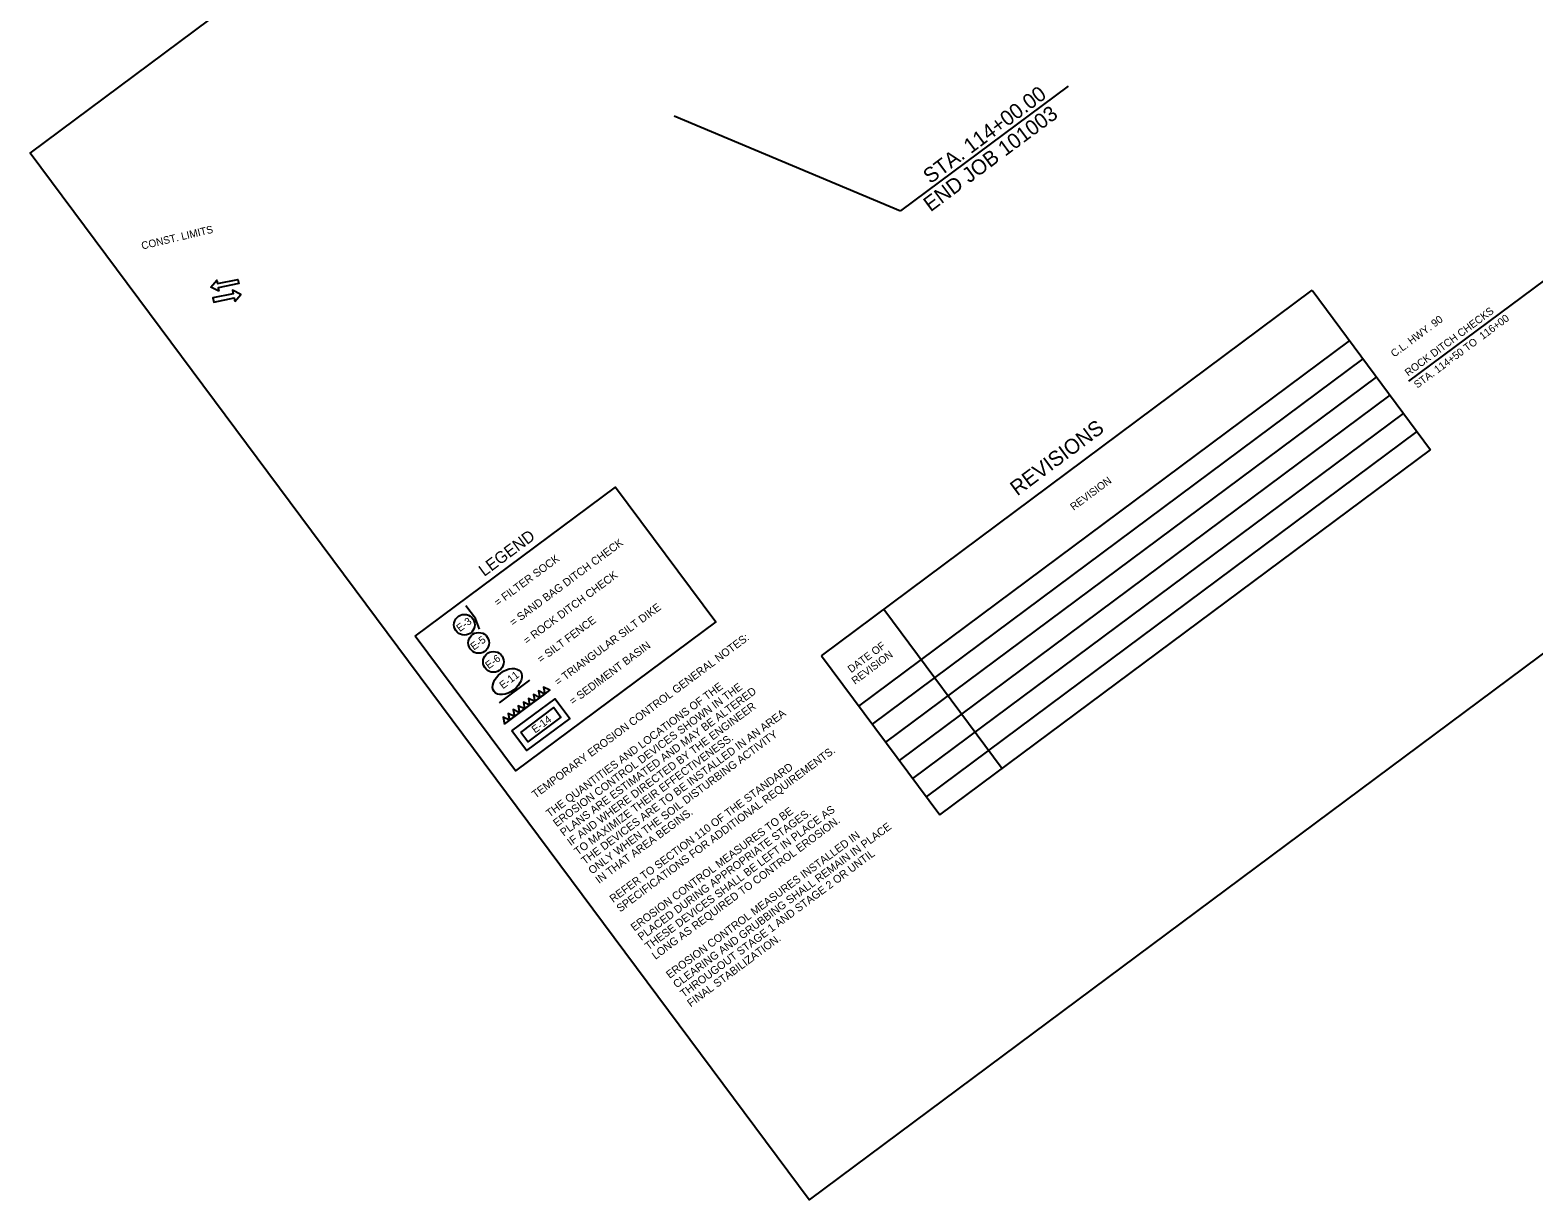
# Model space of a CAD drawing. Extents: x 1571137 to 1573037, y 731597 to 733459.
# Drawn here: x 1571137 to 1572334, y 731597 to 732528 of the extents above; entities that cross this region are included whole.
import ezdxf

# ---------------------------------------------------------------- set-up
doc = ezdxf.new("R2010")
doc.units = 0
for name, color, linetype in [('Default', 7, 'Continuous'), ('R_Annotation', 7, 'Continuous'), ('R_Erosion', 7, 'Continuous'), ('R_Erosion_STG 2', 7, 'Continuous'), ('R_MOT', 7, 'Continuous'), ('S_BASELINE', 7, 'Continuous'), ('S_MSC_PT_SYM', 7, 'Continuous')]:
    doc.layers.add(name, color=color, linetype=linetype)

msp = doc.modelspace()

# ---------------------------------------------------------------- linework, layer by layer
at = {"layer": 'Default'}
msp.add_lwpolyline([(1571510.5, 731992.8), (1571534.7, 732010.8)], dxfattribs=at)
at = {"layer": 'R_Annotation'}
for p, q in [((1571963.2, 732483.5), (1571829.7, 732384.2)), ((1571649.5, 732459.7), (1571829.7, 732384.2)), ((1572234.2, 732248.7), (1572469.2, 732423.5))]:
    msp.add_line(p, q, dxfattribs=at)
msp.add_lwpolyline([(1571443.5, 732045.9), (1571602.8, 732164.5), (1571682.7, 732057.2), (1571523.3, 731938.6)], close=True, dxfattribs=at)
at = {"layer": 'R_Erosion'}
msp.add_line((1571514.5, 731975.9), (1571550.6, 732002.8), dxfattribs=at)
for points in [[(1571494.7, 732051.4), (1571491.4, 732059.8), (1571483.8, 732069.9)], [(1571514.5, 731975.9), (1571550.6, 732002.8)]]:
    msp.add_lwpolyline(points, dxfattribs=at)
for points in [[(1571538.6, 731993.8), (1571542.6, 731996.8), (1571537.6, 731999.3)], [(1571542.6, 731996.8), (1571546.6, 731999.8), (1571541.6, 732002.3)], [(1571546.6, 731999.8), (1571550.6, 732002.8), (1571545.6, 732005.3)], [(1571520.4, 731970.4), (1571554.8, 731996), (1571566.4, 731980.4), (1571532, 731954.8)], [(1571522.5, 731981.9), (1571526.5, 731984.9), (1571521.5, 731987.4)], [(1571526.5, 731984.9), (1571530.5, 731987.9), (1571525.5, 731990.4)], [(1571527.4, 731969.3), (1571553.8, 731989), (1571559.4, 731981.4), (1571533, 731961.8)], [(1571530.5, 731987.9), (1571534.5, 731990.8), (1571529.6, 731993.4)], [(1571534.5, 731990.8), (1571538.6, 731993.8), (1571533.6, 731996.3)], [(1571514.5, 731975.9), (1571518.5, 731978.9), (1571513.5, 731981.4)], [(1571518.5, 731978.9), (1571522.5, 731981.9), (1571517.5, 731984.4)]]:
    msp.add_lwpolyline(points, close=True, dxfattribs=at)
for centre in [(1571482.6, 732054.9), (1571494, 732040.5), (1571505.7, 732025.4)]:
    msp.add_circle(centre, 8.26, dxfattribs=at)
msp.add_ellipse((1571516.7, 732009.7), major_axis=(10.5, 8), ratio=0.638788, dxfattribs=at)
at = {"layer": 'R_MOT'}
for points in [[(1571287.3, 732320.3), (1571280.7, 732323.5), (1571285.5, 732329.1), (1571286.1, 732326.3), (1571302.3, 732329.6), (1571303, 732326.3), (1571286.7, 732323)], [(1571299.8, 732312.2), (1571304.7, 732317.7), (1571298.1, 732321), (1571298.6, 732318.2), (1571282.4, 732315), (1571283.1, 732311.7), (1571299.3, 732314.9)]]:
    msp.add_lwpolyline(points, close=True, dxfattribs=at)
at = {"layer": 'S_BASELINE'}
for p, q in [((1571766.7, 732030.3), (1572157.2, 732321)), ((1572157.2, 732321), (1572251.5, 732194.2)), ((1571796.5, 731990.2), (1572187.1, 732280.9)), ((1571807.3, 731975.8), (1572197.8, 732266.4)), ((1571818, 731961.4), (1572208.5, 732252)), ((1571828.8, 731946.9), (1572219.3, 732237.6)), ((1571839.5, 731932.5), (1572230, 732223.1)), ((1571850.3, 731918), (1572240.8, 732208.7)), ((1571861, 731903.6), (1572251.5, 732194.2)), ((1571816.3, 732067.2), (1571910.6, 731940.5)), ((1571766.7, 732030.3), (1571861, 731903.6))]:
    msp.add_line(p, q, dxfattribs=at)
at = {"layer": 'S_MSC_PT_SYM'}
msp.add_lwpolyline([(1572536.7, 733221.6), (1573036.7, 732549.8), (1571756.9, 731597.3), (1571137, 732430.2), (1572086.8, 733137.2), (1572116.3, 733097.5), (1572258.8, 733203.6), (1572269.5, 733189.2), (1572284.1, 733200.1), (1572282.1, 733202.7), (1572344.4, 733249.1)], dxfattribs=at)

# ---------------------------------------------------------------- texts
at = {"layer": 'Default'}
for s, height, p in [('LEGEND', 9.37, (1571498.4, 732092.9)), ('= SAND BAG DITCH CHECK', 6.25, (1571521.5, 732053.4)), ('= FILTER SOCK', 6.25, (1571509.2, 732069.3)), ('= ROCK DITCH CHECK', 6.25, (1571532.4, 732039)), ('= TRIANGULAR SILT DIKE', 6.25, (1571557.2, 732006.2)), ('= SILT FENCE', 6.25, (1571543.5, 732024.2)), ('= SEDIMENT BASIN', 6.25, (1571569, 731990.8))]:
    msp.add_text(s, height=height, rotation=36.6576, dxfattribs=at).set_placement(p)
at = {"layer": 'R_Annotation'}
for s, height, rotation, p in [('STA. 114+00.00', 12, 36.6576, (1571853.4, 732405.3)), ('END JOB 101003', 12, 36.6576, (1571853.6, 732383)), ('CONST. LIMITS', 6, 13.3424, (1571226.3, 732353.4)), ('C.L. HWY. 90', 6, 36.6576, (1572222.6, 732267.4)), ('ROCK DITCH CHECKS', 6, 36.6576, (1572233.8, 732252.3)), ('STA. 114+50 TO  116+00', 6, 36.6576, (1572241, 732242.7))]:
    msp.add_text(s, height=height, rotation=rotation, dxfattribs=at).set_placement(p)
at = {"layer": 'R_Erosion'}
for s, rotation, p in [('E-3', 36.6576, (1571479, 732049)), ('E-5 ', 36.6576, (1571490.2, 732034.3)), ('E-6 ', 36.6576, (1571502, 732019.4)), ('E-11', 37.2648, (1571513.3, 732003.5)), ('E-14', 36.6576, (1571538.9, 731968.3))]:
    msp.add_text(s, height=6, rotation=rotation, dxfattribs=at).set_placement(p)
at = {"layer": 'R_Erosion_STG 2'}
for s, p in [('TEMPORARY EROSION CONTROL GENERAL NOTES:', (1571539.2, 731916.5)), ('THE QUANTITIES AND LOCATIONS OF THE', (1571550.4, 731901.4)), ('EROSION CONTROL DEVICES SHOWN IN THE ', (1571556.1, 731893.8)), ('PLANS ARE ESTIMATED AND MAY BE ALTERED ', (1571561.7, 731886.3)), ('IF AND WHERE DIRECTED BY THE ENGINEER ', (1571567.3, 731878.7)), ('THE DEVICES ARE TO BE INSTALLED IN AN AREA ', (1571578.5, 731863.7)), ('TO MAXIMIZE THEIR EFFECTIVENESS. ', (1571572.9, 731871.2)), ('ONLY WHEN THE SOIL DISTURBING ACTIVITY', (1571584.2, 731856.1)), ('SPECIFICATIONS FOR ADDITIONAL REQUIREMENTS.', (1571606.6, 731825.9)), ('REFER TO SECTION 110 OF THE STANDARD ', (1571601, 731833.5)), ('IN THAT AREA BEGINS.', (1571589.8, 731848.6)), ('EROSION CONTROL MEASURES TO BE', (1571617.9, 731810.8)), ('PLACED DURING APPROPRIATE STAGES. ', (1571623.5, 731803.3)), ('THESE DEVICES SHALL BE LEFT IN PLACE AS ', (1571629.1, 731795.7)), ('LONG AS REQUIRED TO CONTROL EROSION.', (1571634.7, 731788.2)), ('EROSION CONTROL MEASURES INSTALLED IN', (1571646, 731773.1)), ('CLEARING AND GRUBBING SHALL REMAIN IN PLACE', (1571651.6, 731765.5)), ('THROUGOUT STAGE 1 AND STAGE 2 OR UNTIL', (1571657.2, 731758)), ('FINAL STABILIZATION.', (1571662.8, 731750.4))]:
    msp.add_text(s, height=6.25, rotation=36.6576, dxfattribs=at).set_placement(p)
at = {"layer": 'S_BASELINE'}
for s, height, p in [('REVISIONS', 12, (1571922.6, 732157)), ('REVISION', 6, (1571967.5, 732145.5)), ('DATE OF', 6, (1571790.4, 732016.3)), ('REVISION', 6, (1571793.5, 732007.1))]:
    msp.add_text(s, height=height, rotation=36.6576, dxfattribs=at).set_placement(p)

doc.saveas('drawing.dxf')
